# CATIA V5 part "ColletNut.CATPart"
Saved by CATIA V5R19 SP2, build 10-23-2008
Part number: ColletNut
Revision: ANY
Definition: UNKNOWN
Nomenclature: ColletNut
Source: Unknown
Bounding box of the stored display mesh (mm): x -12.702 to 12.702, y 0 to 12, z -11 to 11
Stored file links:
  Z:\fausse table rondelle-20220905T211342Z-001\fausse table rondelle\ColletNut.CATPart
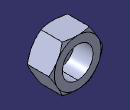
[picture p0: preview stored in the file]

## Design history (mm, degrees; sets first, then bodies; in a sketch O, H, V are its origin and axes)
AxisSystem1: origin (0, 0, 0), X (1, 0, 0), Y (0, 1, 0), Z (0, 0, 1)
Body1 "Schnitt-Rotation1" (main body)
  Solid1: solid without history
